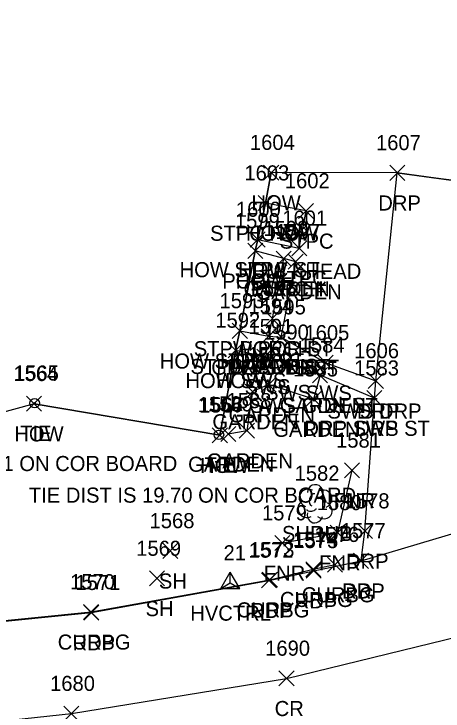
# Model space of a CAD drawing. Extents: x 1638344 to 1639591, y 610835 to 612202.
# Drawn here: x 1638413 to 1638469.9, y 611608.8 to 611701.2 of the extents above; entities that cross this region are included whole.
import ezdxf

# ---------------------------------------------------------------- set-up
doc = ezdxf.new("R2010")
doc.units = 0
for name, color, linetype in [('C_A', 7, 'Continuous'), ('C_C', 7, 'Continuous'), ('C_I', 7, 'Continuous'), ('CBP', 7, 'Continuous'), ('CPSM', 7, 'Continuous'), ('L_A', 7, 'Continuous'), ('L_C', 7, 'Continuous'), ('L_I', 7, 'Continuous'), ('L_TIC', 7, 'Continuous'), ('LAPB', 7, 'Continuous'), ('LBC', 7, 'Continuous'), ('LBF', 7, 'Continuous'), ('LFNC', 7, 'Continuous'), ('LSH', 7, 'Continuous'), ('LSOGP', 7, 'Continuous'), ('P_A', 7, 'Continuous'), ('P_I', 7, 'Continuous'), ('P_TIC', 7, 'Continuous'), ('PET', 7, 'Continuous'), ('PRC', 7, 'Continuous'), ('R_A', 7, 'Continuous'), ('R_I', 7, 'Continuous'), ('R_TIC', 7, 'Continuous'), ('RC', 7, 'Continuous'), ('RDP', 7, 'Continuous'), ('RSW', 7, 'Continuous')]:
    doc.layers.add(name, color=color, linetype=linetype)

msp = doc.modelspace()

# ---------------------------------------------------------------- linework, layer by layer
at = {"layer": 'CBP'}
for centre, radius in [((1638415.746, 611649.595), 0.625), ((1638415.746, 611649.595), 0.0833), ((1638440.186, 611645.405), 0.625), ((1638440.186, 611645.405), 0.0833)]:
    msp.add_circle(centre, radius, dxfattribs=at)
at = {"layer": 'CPSM'}
for p, q in [((1638440.435, 611625.044), (1638441.685, 611627.209)), ((1638440.435, 611625.044), (1638441.685, 611627.209)), ((1638440.435, 611625.044), (1638441.685, 611627.209)), ((1638440.435, 611625.044), (1638441.685, 611627.209)), ((1638440.435, 611625.044), (1638441.685, 611627.209)), ((1638440.435, 611625.044), (1638441.685, 611627.209)), ((1638440.435, 611625.044), (1638441.685, 611627.209)), ((1638442.935, 611625.044), (1638441.685, 611627.209)), ((1638441.685, 611625.765), (1638441.685, 611627.209)), ((1638442.935, 611625.044), (1638441.685, 611627.209)), ((1638441.685, 611625.765), (1638441.685, 611627.209)), ((1638442.935, 611625.044), (1638441.685, 611627.209)), ((1638441.685, 611625.765), (1638441.685, 611627.209)), ((1638442.935, 611625.044), (1638441.685, 611627.209)), ((1638441.685, 611625.765), (1638441.685, 611627.209)), ((1638442.935, 611625.044), (1638441.685, 611627.209)), ((1638441.685, 611625.765), (1638441.685, 611627.209)), ((1638442.935, 611625.044), (1638441.685, 611627.209)), ((1638441.685, 611625.765), (1638441.685, 611627.209)), ((1638442.935, 611625.044), (1638441.685, 611627.209)), ((1638441.685, 611625.765), (1638441.685, 611627.209)), ((1638440.435, 611625.044), (1638441.685, 611625.765)), ((1638440.435, 611625.044), (1638441.685, 611625.765)), ((1638440.435, 611625.044), (1638441.685, 611625.765)), ((1638440.435, 611625.044), (1638441.685, 611625.765)), ((1638440.435, 611625.044), (1638441.685, 611625.765)), ((1638440.435, 611625.044), (1638441.685, 611625.765)), ((1638440.435, 611625.044), (1638441.685, 611625.765)), ((1638441.685, 611625.765), (1638441.685, 611625.765)), ((1638441.685, 611625.765), (1638442.935, 611625.044)), ((1638441.685, 611625.765), (1638441.685, 611625.765)), ((1638441.685, 611625.765), (1638442.935, 611625.044)), ((1638441.685, 611625.765), (1638441.685, 611625.765)), ((1638441.685, 611625.765), (1638442.935, 611625.044)), ((1638441.685, 611625.765), (1638441.685, 611625.765)), ((1638441.685, 611625.765), (1638442.935, 611625.044)), ((1638441.685, 611625.765), (1638441.685, 611625.765)), ((1638441.685, 611625.765), (1638442.935, 611625.044)), ((1638441.685, 611625.765), (1638441.685, 611625.765)), ((1638441.685, 611625.765), (1638442.935, 611625.044)), ((1638441.685, 611625.765), (1638441.685, 611625.765)), ((1638441.685, 611625.765), (1638442.935, 611625.044)), ((1638440.435, 611625.044), (1638442.935, 611625.044)), ((1638440.435, 611625.044), (1638442.935, 611625.044)), ((1638440.435, 611625.044), (1638442.935, 611625.044)), ((1638440.435, 611625.044), (1638442.935, 611625.044)), ((1638440.435, 611625.044), (1638442.935, 611625.044)), ((1638440.435, 611625.044), (1638442.935, 611625.044)), ((1638440.435, 611625.044), (1638442.935, 611625.044))]:
    msp.add_line(p, q, dxfattribs=at)
at = {"layer": 'L_TIC'}
for points in [[(1638446.11, 611679.16), (1638448.11, 611681.16)], [(1638448.11, 611679.16), (1638446.11, 611681.16)], [(1638445.375, 611675.119), (1638447.375, 611677.119)], [(1638447.375, 611675.119), (1638445.375, 611677.119)], [(1638445.375, 611675.119), (1638447.375, 611677.119)], [(1638447.375, 611675.119), (1638445.375, 611677.119)], [(1638450.742, 611674.074), (1638452.742, 611676.074)], [(1638452.742, 611674.074), (1638450.742, 611676.074)], [(1638444.334, 611670.295), (1638446.334, 611672.295)], [(1638446.334, 611670.295), (1638444.334, 611672.295)], [(1638444.334, 611670.295), (1638446.334, 611672.295)], [(1638446.334, 611670.295), (1638444.334, 611672.295)], [(1638449.835, 611669.133), (1638451.835, 611671.133)], [(1638451.835, 611669.133), (1638449.835, 611671.133)], [(1638444.002, 611668.783), (1638446.002, 611670.783)], [(1638446.002, 611668.783), (1638444.002, 611670.783)], [(1638444.002, 611668.783), (1638446.002, 611670.783)], [(1638446.002, 611668.783), (1638444.002, 611670.783)], [(1638447.768, 611667.753), (1638449.768, 611669.753)], [(1638449.768, 611667.753), (1638447.768, 611669.753)], [(1638447.768, 611667.753), (1638449.768, 611669.753)], [(1638449.768, 611667.753), (1638447.768, 611669.753)], [(1638449.358, 611667.347), (1638451.358, 611669.347)], [(1638451.358, 611667.347), (1638449.358, 611669.347)], [(1638446.263, 611659.814), (1638448.263, 611661.814)], [(1638448.263, 611659.814), (1638446.263, 611661.814)], [(1638446.263, 611659.814), (1638448.263, 611661.814)], [(1638448.263, 611659.814), (1638446.263, 611661.814)], [(1638441.954, 611658.181), (1638443.954, 611660.181)], [(1638443.954, 611658.181), (1638441.954, 611660.181)], [(1638441.954, 611658.181), (1638443.954, 611660.181)], [(1638443.954, 611658.181), (1638441.954, 611660.181)], [(1638445.786, 611657.469), (1638447.786, 611659.469)], [(1638447.786, 611657.469), (1638445.786, 611659.469)], [(1638445.786, 611657.469), (1638447.786, 611659.469)], [(1638447.786, 611657.469), (1638445.786, 611659.469)], [(1638447.446, 611657.359), (1638449.446, 611659.359)], [(1638449.446, 611657.359), (1638447.446, 611659.359)], [(1638441.394, 611655.587), (1638443.394, 611657.587)], [(1638443.394, 611655.587), (1638441.394, 611657.587)], [(1638452.584, 611652.302), (1638454.584, 611654.302)], [(1638454.584, 611652.302), (1638452.584, 611654.302)], [(1638445.792, 611651.052), (1638447.792, 611653.052)], [(1638447.792, 611651.052), (1638445.792, 611653.052)], [(1638443.643, 611650.132), (1638445.643, 611652.132)], [(1638445.643, 611650.132), (1638443.643, 611652.132)], [(1638451.719, 611649.133), (1638453.719, 611651.133)], [(1638453.719, 611649.133), (1638451.719, 611651.133)], [(1638414.664, 611648.528), (1638416.664, 611650.528)], [(1638416.664, 611648.528), (1638414.664, 611650.528)], [(1638439.297, 611644.344), (1638441.297, 611646.344)], [(1638441.297, 611644.344), (1638439.297, 611646.344)], [(1638440.423, 611644.503), (1638442.423, 611646.503)], [(1638442.423, 611644.503), (1638440.423, 611646.503)], [(1638442.878, 611644.936), (1638444.878, 611646.936)], [(1638444.878, 611644.936), (1638442.878, 611646.936)], [(1638456.841, 611639.699), (1638458.841, 611641.699)], [(1638458.841, 611639.699), (1638456.841, 611641.699)], [(1638454.936, 611631.416), (1638456.936, 611633.416)], [(1638456.936, 611631.416), (1638454.936, 611633.416)], [(1638447.59, 611630.061), (1638449.59, 611632.061)], [(1638449.59, 611630.061), (1638447.59, 611632.061)], [(1638432.727, 611629.021), (1638434.727, 611631.021)], [(1638434.727, 611629.021), (1638432.727, 611631.021)], [(1638430.963, 611625.363), (1638432.963, 611627.363)], [(1638432.963, 611625.363), (1638430.963, 611627.363)]]:
    msp.add_lwpolyline(points, dxfattribs=at)
at = {"layer": 'LAPB'}
for points in [[(1638446.786, 611658.469), (1638448.446, 611658.359), (1638450.358, 611668.347), (1638448.768, 611668.753)], [(1638453.584, 611653.302), (1638452.719, 611650.133), (1638446.792, 611652.052), (1638444.643, 611651.132), (1638443.878, 611645.936), (1638441.423, 611645.503)]]:
    msp.add_lwpolyline(points, dxfattribs=at)
at = {"layer": 'LBC'}
msp.add_lwpolyline([(1638415.664, 611649.528), (1638440.297, 611645.344), (1638442.394, 611656.587), (1638442.954, 611659.181), (1638445.002, 611669.783), (1638445.334, 611671.295), (1638446.375, 611676.119), (1638447.11, 611680.16)], dxfattribs=at)
at = {"layer": 'LBF'}
for points in [[(1638445.334, 611671.295), (1638450.835, 611670.133), (1638451.742, 611675.074), (1638446.375, 611676.119)], [(1638447.263, 611660.814), (1638448.768, 611668.753), (1638445.002, 611669.783)], [(1638442.954, 611659.181), (1638446.786, 611658.469), (1638447.263, 611660.814)]]:
    msp.add_lwpolyline(points, dxfattribs=at)
at = {"layer": 'LFNC'}
msp.add_lwpolyline([(1638448.59, 611631.061), (1638455.936, 611632.416), (1638457.841, 611640.699)], dxfattribs=at)
at = {"layer": 'LSH'}
msp.add_line((1638452.91, 611636.316), (1638452.91, 611636.316), dxfattribs=at)
msp.add_line((1638452.91, 611636.316), (1638452.91, 611636.316), dxfattribs=at)
msp.add_arc((1638452.957, 611637.75), 1.047, 335.52715, 180.95627, dxfattribs=at)
for centre, major_axis, ratio, start_param, end_param in [((1638452.118, 611636.982), (1.21, -0.512), 0.895232, 1.570796, 4.712389), ((1638453.952, 611636.899), (-1.141, -0.483), 0.949671, 1.570796, 4.712389), ((1638452.702, 611636.774), (-0.208, -0.792), 0.645439, 3.141593, 6.283185), ((1638453.41, 611636.149), (-0.5, 0.667), 0.989748, 3.141593, 6.283185), ((1638451.827, 611635.607), (0.584, -1.042), 0.959034, 3.141593, 6.283185), ((1638453.91, 611635.483), (-1.09, 0.792), 0.841452, 1.570796, 4.712389), ((1638452.91, 611634.816), (0.265, 1.061), 0.942809, 1.570796, 4.712389), ((1638452.452, 611635.566), (-0.625, -0.083), 0.423636, 0, 3.141593)]:
    msp.add_ellipse(centre, major_axis=major_axis, ratio=ratio, start_param=start_param, end_param=end_param, dxfattribs=at)
at = {"layer": 'LSOGP'}
msp.add_lwpolyline([(1638544.314, 611701.186), (1638525.151, 611698.678), (1638515.691, 611695.593), (1638507.499, 611686.096), (1638493.208, 611681.381), (1638484.312, 611677.361), (1638479.191, 611678.053), (1638474.069, 611678.745), (1638468.947, 611679.437), (1638463.825, 611680.129), (1638447.11, 611680.16), (1638446.375, 611676.119), (1638445.334, 611671.295), (1638445.002, 611669.783), (1638442.954, 611659.181), (1638442.394, 611656.587), (1638440.297, 611645.344), (1638415.664, 611649.528), (1638379.03, 611639.471), (1638358.66, 611627.132), (1638355.83, 611619.706), (1638355.881, 611616.997), (1638356.118, 611602.692)], dxfattribs=at)
at = {"layer": 'P_TIC'}
for points in [[(1638458.034, 611627.698), (1638460.034, 611629.698)], [(1638460.034, 611627.698), (1638458.034, 611629.698)], [(1638451.746, 611626.381), (1638453.746, 611628.381)], [(1638453.746, 611626.381), (1638451.746, 611628.381)], [(1638445.809, 611625.112), (1638447.809, 611627.112)], [(1638447.809, 611625.112), (1638445.809, 611627.112)], [(1638422.276, 611620.83), (1638424.276, 611622.83)], [(1638424.276, 611620.83), (1638422.276, 611622.83)], [(1638448.138, 611612.12), (1638450.138, 611614.12)], [(1638450.138, 611612.12), (1638448.138, 611614.12)], [(1638419.617, 611607.455), (1638421.617, 611609.455)], [(1638421.617, 611607.455), (1638419.617, 611609.455)]]:
    msp.add_lwpolyline(points, dxfattribs=at)
at = {"layer": 'PET'}
msp.add_lwpolyline([(1638355.97, 611616.931), (1638384.535, 611618.591), (1638398.864, 611619.61), (1638400.74, 611618.429), (1638405.64, 611618.566), (1638407.823, 611620.304), (1638423.276, 611621.83), (1638446.809, 611626.112), (1638452.746, 611627.381), (1638459.034, 611628.698), (1638481.778, 611635.472), (1638483.493, 611635.844), (1638487.217, 611637.218), (1638500.055, 611642.229), (1638515.475, 611648.95), (1638537.758, 611659.278), (1638554.291, 611667.168), (1638564.39, 611672.354), (1638583.677, 611682.572)], dxfattribs=at)
at = {"layer": 'PRC'}
msp.add_lwpolyline([(1638356.118, 611602.692), (1638388.659, 611605.003), (1638420.617, 611608.455), (1638449.138, 611613.12), (1638473.926, 611619.145), (1638495.393, 611626.423), (1638517.33, 611635.581), (1638540.468, 611646.456), (1638560.014, 611656.083), (1638583.711, 611667.643), (1638612.695, 611681.655), (1638628.785, 611688.734), (1638636.085, 611691.336), (1638643.826, 611693.958)], dxfattribs=at)
at = {"layer": 'R_TIC'}
for points in [[(1638462.825, 611679.129), (1638464.825, 611681.129)], [(1638464.825, 611679.129), (1638462.825, 611681.129)], [(1638447.446, 611657.359), (1638449.446, 611659.359)], [(1638449.446, 611657.359), (1638447.446, 611659.359)], [(1638441.394, 611655.587), (1638443.394, 611657.587)], [(1638443.394, 611655.587), (1638441.394, 611657.587)], [(1638445.22, 611654.773), (1638447.22, 611656.773)], [(1638447.22, 611654.773), (1638445.22, 611656.773)], [(1638447.929, 611654.019), (1638449.929, 611656.019)], [(1638449.929, 611654.019), (1638447.929, 611656.019)], [(1638453.341, 611653.94), (1638455.341, 611655.94)], [(1638455.341, 611653.94), (1638453.341, 611655.94)], [(1638452.584, 611652.302), (1638454.584, 611654.302)], [(1638454.584, 611652.302), (1638452.584, 611654.302)], [(1638459.985, 611651.553), (1638461.985, 611653.553)], [(1638461.985, 611651.553), (1638459.985, 611653.553)], [(1638459.985, 611651.553), (1638461.985, 611653.553)], [(1638461.985, 611651.553), (1638459.985, 611653.553)], [(1638459.801, 611649.264), (1638461.801, 611651.264)], [(1638461.801, 611649.264), (1638459.801, 611651.264)], [(1638459.801, 611649.264), (1638461.801, 611651.264)], [(1638461.801, 611649.264), (1638459.801, 611651.264)], [(1638458.547, 611631.651), (1638460.547, 611633.651)], [(1638460.547, 611631.651), (1638458.547, 611633.651)], [(1638458.034, 611627.698), (1638460.034, 611629.698)], [(1638460.034, 611627.698), (1638458.034, 611629.698)], [(1638451.685, 611626.579), (1638453.685, 611628.579)], [(1638453.685, 611626.579), (1638451.685, 611628.579)], [(1638454.581, 611627.199), (1638456.581, 611629.199)], [(1638456.581, 611627.199), (1638454.581, 611629.199)], [(1638445.934, 611625.195), (1638447.934, 611627.195)], [(1638447.934, 611625.195), (1638445.934, 611627.195)], [(1638422.221, 611620.93), (1638424.221, 611622.93)], [(1638424.221, 611620.93), (1638422.221, 611622.93)]]:
    msp.add_lwpolyline(points, dxfattribs=at)
at = {"layer": 'RC'}
msp.add_lwpolyline([(1638355.881, 611616.997), (1638384.628, 611618.68), (1638398.803, 611619.735), (1638401.147, 611621.492), (1638405.101, 611621.707), (1638407.825, 611620.383), (1638423.221, 611621.93), (1638446.934, 611626.195), (1638452.685, 611627.579), (1638455.581, 611628.199)], dxfattribs=at)
at = {"layer": 'RDP'}
msp.add_lwpolyline([(1638459.034, 611628.698), (1638459.547, 611632.651), (1638460.801, 611650.264), (1638460.985, 611652.553), (1638463.825, 611680.129), (1638484.312, 611677.361), (1638482.104, 611657.177), (1638480.565, 611639.923), (1638480.829, 611637.005), (1638481.778, 611635.472)], dxfattribs=at)
at = {"layer": 'RSW'}
for points in [[(1638448.446, 611658.359), (1638454.341, 611654.94), (1638460.985, 611652.553)], [(1638460.801, 611650.264), (1638453.584, 611653.302), (1638448.929, 611655.019), (1638446.22, 611655.773), (1638442.394, 611656.587)]]:
    msp.add_lwpolyline(points, dxfattribs=at)

# ---------------------------------------------------------------- texts
at = {"layer": 'C_A'}
for s, p in [('TIE', (1638413.825, 611644.595)), ('TIE', (1638438.264, 611640.405)), ('HVCTRL', (1638436.378, 611620.765)), ('HVCTRL', (1638436.378, 611620.765)), ('HVCTRL', (1638436.378, 611620.765)), ('HVCTRL', (1638436.378, 611620.765)), ('HVCTRL', (1638436.378, 611620.765)), ('HVCTRL', (1638436.378, 611620.765)), ('HVCTRL', (1638436.378, 611620.765))]:
    msp.add_text(s, height=2, dxfattribs=at).set_placement(p)
at = {"layer": 'C_C'}
for s, p in [('TIE DIST IS 35.21 ON COR BOARD', (1638391.266, 611640.595)), ('TIE DIST IS 19.70 ON COR BOARD', (1638414.981, 611636.405))]:
    msp.add_text(s, height=2, dxfattribs=at).set_placement(p)
at = {"layer": 'C_I'}
for s, p in [('1565', (1638413.006, 611652.595)), ('1566', (1638437.39, 611648.405)), ('21', (1638440.787, 611628.765)), ('21', (1638440.787, 611628.765)), ('21', (1638440.787, 611628.765)), ('21', (1638440.787, 611628.765)), ('21', (1638440.787, 611628.765)), ('21', (1638440.787, 611628.765)), ('21', (1638440.787, 611628.765))]:
    msp.add_text(s, height=2, dxfattribs=at).set_placement(p)
at = {"layer": 'L_A'}
for s, p in [('HOW', (1638444.496, 611675.16)), ('STPC HOW', (1638439.005, 611671.119)), ('HOW', (1638443.761, 611671.119)), ('STPC', (1638448.253, 611670.074)), ('HOW STPC ST', (1638434.964, 611666.295)), ('HOW', (1638442.72, 611666.295)), ('PORCH', (1638440.624, 611664.783)), ('HOW', (1638442.388, 611664.783)), ('STPC', (1638447.347, 611665.133)), ('GARDEN', (1638443.437, 611663.753)), ('PORCH', (1638444.39, 611663.753)), ('GARDEN', (1638445.027, 611663.347)), ('STPW POR ST', (1638436.845, 611655.814)), ('PORCH', (1638442.885, 611655.814)), ('HOW STPW ST', (1638432.332, 611654.181)), ('HOW', (1638440.339, 611654.181)), ('STPW GDN ST', (1638436.4, 611653.469)), ('GARDEN', (1638441.455, 611653.469)), ('GARDEN', (1638443.115, 611653.359)), ('HOW', (1638439.779, 611651.587)), ('GARDEN', (1638448.254, 611648.302)), ('GARDEN', (1638441.461, 611647.052)), ('GARDEN', (1638439.312, 611646.132)), ('GARDEN', (1638447.388, 611645.133)), ('HOW', (1638413.05, 611644.528)), ('GARDEN', (1638436.093, 611640.503)), ('HOW', (1638437.683, 611640.344)), ('GARDEN', (1638438.548, 611640.936)), ('FNR', (1638455.376, 611635.699)), ('SHRUB', (1638448.54, 611631.316)), ('FNR', (1638453.472, 611627.416)), ('FNR', (1638446.125, 611626.061)), ('SH', (1638432.216, 611625.021)), ('SH', (1638430.451, 611621.363))]:
    msp.add_text(s, height=2, dxfattribs=at).set_placement(p)
at = {"layer": 'L_C'}
msp.add_text('BULKHEAD', height=2, dxfattribs=at).set_placement((1638444.647, 611666.074))
at = {"layer": 'L_I'}
for s, p in [('1604', (1638444.291, 611683.16)), ('1603', (1638443.556, 611679.119)), ('1603', (1638443.556, 611679.119)), ('1602', (1638448.923, 611678.074)), ('1600', (1638442.429, 611674.295)), ('1600', (1638442.429, 611674.295)), ('1599', (1638442.301, 611672.783)), ('1599', (1638442.301, 611672.783)), ('1601', (1638448.583, 611673.133)), ('1598', (1638446.075, 611671.753)), ('1598', (1638446.075, 611671.753)), ('1597', (1638447.665, 611671.347)), ('1596', (1638444.515, 611663.814)), ('1596', (1638444.515, 611663.814)), ('1593', (1638440.261, 611662.181)), ('1593', (1638440.261, 611662.181)), ('1594', (1638444.093, 611661.469)), ('1594', (1638444.093, 611661.469)), ('1595', (1638445.753, 611661.359)), ('1592', (1638439.701, 611659.587)), ('1584', (1638450.892, 611656.302)), ('1586', (1638444.044, 611655.052)), ('1587', (1638441.95, 611654.132)), ('1564', (1638412.924, 611652.528)), ('1585', (1638450.026, 611653.133)), ('1588', (1638441.185, 611648.936)), ('1567', (1638437.557, 611648.344)), ('1589', (1638438.723, 611648.503)), ('1581', (1638455.715, 611643.699)), ('1582', (1638450.217, 611639.316)), ('1580', (1638453.157, 611635.416)), ('1579', (1638445.889, 611634.061)), ('1568', (1638430.987, 611633.021)), ('1569', (1638429.215, 611629.363))]:
    msp.add_text(s, height=2, dxfattribs=at).set_placement(p)
at = {"layer": 'P_A'}
for s, p in [('RDP', (1638456.522, 611623.698)), ('RDP', (1638450.234, 611622.381)), ('RDP', (1638444.297, 611621.112)), ('RDP', (1638420.765, 611616.83)), ('CR', (1638447.571, 611608.12))]:
    msp.add_text(s, height=2, dxfattribs=at).set_placement(p)
at = {"layer": 'P_I'}
for s, p in [('1577', (1638456.341, 611631.698)), ('1575', (1638450.053, 611630.381)), ('1572', (1638444.116, 611629.112)), ('1571', (1638421.15, 611624.83)), ('1690', (1638446.311, 611616.12)), ('1680', (1638417.79, 611611.455))]:
    msp.add_text(s, height=2, dxfattribs=at).set_placement(p)
at = {"layer": 'R_A'}
for s, p in [('DRP', (1638461.313, 611675.129)), ('GDN SWS ST', (1638439.163, 611653.359)), ('HOW SWS', (1638435.748, 611651.587)), ('SWS', (1638443.59, 611650.773)), ('SWS', (1638446.299, 611650.019)), ('SWS', (1638451.711, 611649.94)), ('SWS GDN ST', (1638444.301, 611648.302)), ('SWS DRP', (1638454.568, 611647.553)), ('DRP', (1638458.473, 611647.553)), ('DRP SWS ST', (1638451.517, 611645.264)), ('DRP', (1638458.289, 611645.264)), ('DRP', (1638457.035, 611627.651)), ('DRP', (1638456.522, 611623.698)), ('CURBG', (1638451.164, 611623.199)), ('CURBG', (1638448.267, 611622.579)), ('CURBG', (1638442.517, 611621.195)), ('CURBG', (1638418.803, 611616.93))]:
    msp.add_text(s, height=2, dxfattribs=at).set_placement(p)
at = {"layer": 'R_I'}
for s, p in [('1607', (1638461.006, 611683.129)), ('1595', (1638445.753, 611661.359)), ('1592', (1638439.701, 611659.587)), ('1591', (1638444.094, 611658.773)), ('1590', (1638446.15, 611658.019)), ('1605', (1638451.522, 611657.94)), ('1584', (1638450.892, 611656.302)), ('1606', (1638458.111, 611655.553)), ('1606', (1638458.111, 611655.553)), ('1583', (1638458.108, 611653.264)), ('1583', (1638458.108, 611653.264)), ('1578', (1638456.854, 611635.651)), ('1576', (1638452.833, 611631.199)), ('1577', (1638456.341, 611631.698)), ('1574', (1638449.992, 611630.579)), ('1573', (1638444.242, 611629.195)), ('1570', (1638420.441, 611624.93))]:
    msp.add_text(s, height=2, dxfattribs=at).set_placement(p)

doc.saveas('drawing.dxf')
